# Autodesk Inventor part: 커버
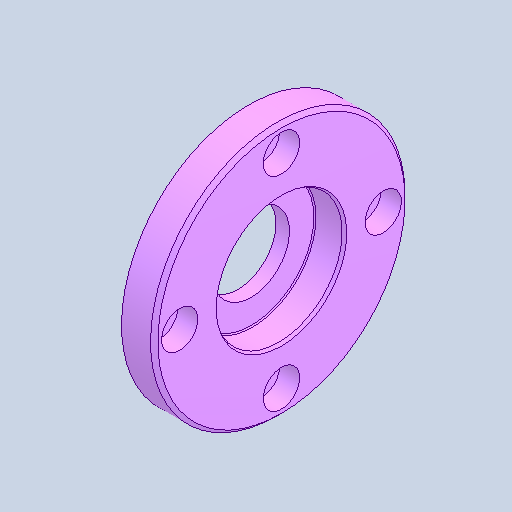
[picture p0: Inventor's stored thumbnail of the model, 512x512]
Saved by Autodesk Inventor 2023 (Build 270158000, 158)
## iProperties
Created: 2024-09
Part Number: 커버
Material: 알루미늄 6061
Document SubType Name: Modeling
Designer: home
Density: 2.7 g/cm^3
Appearance: 기본값
Author: jhkim
Sending System: Autodesk Inventor 2025
Preprocessor: ST-DEVELOPER v20
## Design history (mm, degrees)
feature "솔리드1"
node "솔리드2"
